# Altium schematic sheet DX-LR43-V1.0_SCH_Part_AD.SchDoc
size 431 x 279 mm; SchematicName: $$$NONE
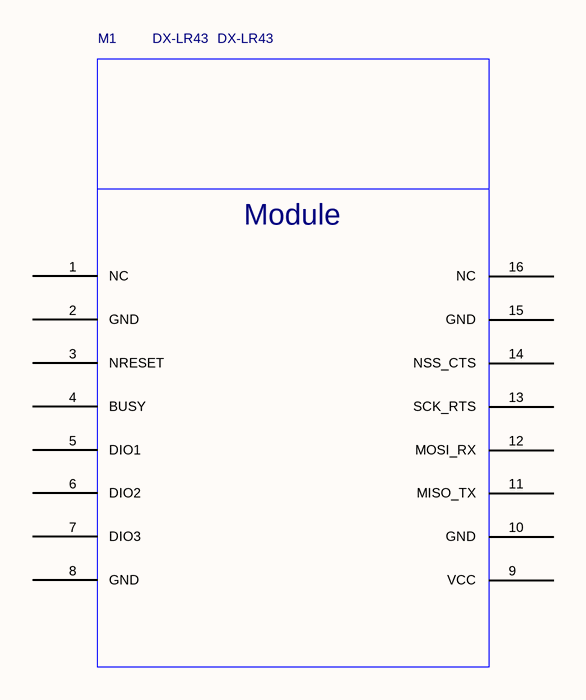
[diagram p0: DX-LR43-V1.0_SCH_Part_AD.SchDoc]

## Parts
M1  DX-LR43  [DX-LR43]

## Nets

Not connected (* = marked no-connect by the designer): M1 1(NC) 2(GND) 3(NRESET) 4(BUSY) 5(DIO1) 6(DIO2) 7(DIO3) 8(GND) 9(VCC) 10(GND) 11(MISO_TX) 12(MOSI_RX) 13(SCK_RTS) 14(NSS_CTS) 15(GND) 16(NC)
